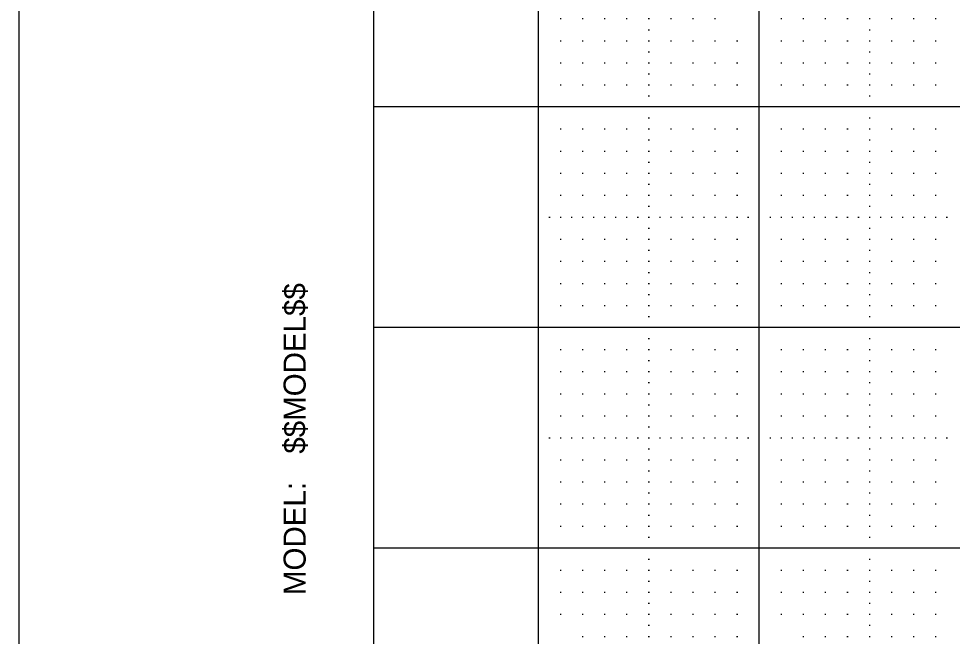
# Model space of a CAD drawing. Extents: x -1.3 to 32.7, y -0.7 to 21.3.
# Drawn here: x -1.263 to 2.967, y 4.893 to 7.693 of the extents above; entities that cross this region are included whole.
import ezdxf

# ---------------------------------------------------------------- set-up
doc = ezdxf.new("R2010")
doc.units = 0
for name, color, linetype in [('Level 1', 7, 'Continuous'), ('Level 5', 7, 'Continuous'), ('Level 63', 7, 'Continuous'), ('R_Border_Dark', 7, 'Continuous')]:
    doc.layers.add(name, color=color, linetype=linetype)

msp = doc.modelspace()

# ---------------------------------------------------------------- linework, layer by layer
at = {"layer": 'Level 1'}
for p, q in [((-1.263, 21.273), (-1.263, -0.727)), ((0.3463, -0.001), (0.3463, 20.545))]:
    msp.add_line(p, q, dxfattribs=at)
at = {"layer": 'Level 5'}
for p, q in [((1.1898, 7.693), (1.1948, 7.693)), ((1.2898, 7.693), (1.2948, 7.693)), ((1.3898, 7.693), (1.3948, 7.693)), ((1.4898, 7.693), (1.4948, 7.693)), ((1.5898, 7.693), (1.5948, 7.693)), ((1.6898, 7.693), (1.6948, 7.693)), ((1.7898, 7.693), (1.7948, 7.693)), ((1.8898, 7.693), (1.8948, 7.693)), ((2.1898, 7.693), (2.1948, 7.693)), ((2.2898, 7.693), (2.2948, 7.693)), ((2.3898, 7.693), (2.3948, 7.693)), ((2.4898, 7.693), (2.4948, 7.693)), ((2.5898, 7.693), (2.5948, 7.693)), ((2.6898, 7.693), (2.6948, 7.693)), ((2.7898, 7.693), (2.7948, 7.693)), ((2.8898, 7.693), (2.8948, 7.693)), ((1.5898, 7.643), (1.5948, 7.643)), ((2.5898, 7.643), (2.5948, 7.643)), ((1.1898, 7.593), (1.1948, 7.593)), ((1.2898, 7.593), (1.2948, 7.593)), ((1.3898, 7.593), (1.3948, 7.593)), ((1.4898, 7.593), (1.4948, 7.593)), ((1.5898, 7.593), (1.5948, 7.593)), ((1.6898, 7.593), (1.6948, 7.593)), ((1.7898, 7.593), (1.7948, 7.593)), ((1.8898, 7.593), (1.8948, 7.593)), ((1.9898, 7.593), (1.9948, 7.593)), ((2.1898, 7.593), (2.1948, 7.593)), ((2.2898, 7.593), (2.2948, 7.593)), ((2.3898, 7.593), (2.3948, 7.593)), ((2.4898, 7.593), (2.4948, 7.593)), ((2.5898, 7.593), (2.5948, 7.593)), ((2.6898, 7.593), (2.6948, 7.593)), ((2.7898, 7.593), (2.7948, 7.593)), ((2.8898, 7.593), (2.8948, 7.593)), ((1.5898, 7.543), (1.5948, 7.543)), ((2.5898, 7.543), (2.5948, 7.543)), ((1.1898, 7.493), (1.1948, 7.493)), ((1.2898, 7.493), (1.2948, 7.493)), ((1.3898, 7.493), (1.3948, 7.493)), ((1.4898, 7.493), (1.4948, 7.493)), ((1.5898, 7.493), (1.5948, 7.493)), ((1.6898, 7.493), (1.6948, 7.493)), ((1.7898, 7.493), (1.7948, 7.493)), ((1.8898, 7.493), (1.8948, 7.493)), ((1.9898, 7.493), (1.9948, 7.493)), ((2.1898, 7.493), (2.1948, 7.493)), ((2.2898, 7.493), (2.2948, 7.493)), ((2.3898, 7.493), (2.3948, 7.493)), ((2.4898, 7.493), (2.4948, 7.493)), ((2.5898, 7.493), (2.5948, 7.493)), ((2.6898, 7.493), (2.6948, 7.493)), ((2.7898, 7.493), (2.7948, 7.493)), ((2.8898, 7.493), (2.8948, 7.493)), ((1.5898, 7.443), (1.5948, 7.443)), ((2.5898, 7.443), (2.5948, 7.443)), ((1.1898, 7.393), (1.1948, 7.393)), ((1.2898, 7.393), (1.2948, 7.393)), ((1.3898, 7.393), (1.3948, 7.393)), ((1.4898, 7.393), (1.4948, 7.393)), ((1.5898, 7.393), (1.5948, 7.393)), ((1.6898, 7.393), (1.6948, 7.393)), ((1.7898, 7.393), (1.7948, 7.393)), ((1.8898, 7.393), (1.8948, 7.393)), ((1.9898, 7.393), (1.9948, 7.393)), ((2.1898, 7.393), (2.1948, 7.393)), ((2.2898, 7.393), (2.2948, 7.393)), ((2.3898, 7.393), (2.3948, 7.393)), ((2.4898, 7.393), (2.4948, 7.393)), ((2.5898, 7.393), (2.5948, 7.393)), ((2.6898, 7.393), (2.6948, 7.393)), ((2.7898, 7.393), (2.7948, 7.393)), ((2.8898, 7.393), (2.8948, 7.393)), ((1.5898, 7.343), (1.5948, 7.343)), ((2.5898, 7.343), (2.5948, 7.343)), ((1.5898, 7.243), (1.5948, 7.243)), ((2.5898, 7.243), (2.5948, 7.243)), ((1.1898, 7.193), (1.1948, 7.193)), ((1.2898, 7.193), (1.2948, 7.193)), ((1.3898, 7.193), (1.3948, 7.193)), ((1.4898, 7.193), (1.4948, 7.193)), ((1.5898, 7.193), (1.5948, 7.193)), ((1.6898, 7.193), (1.6948, 7.193)), ((1.7898, 7.193), (1.7948, 7.193)), ((1.8898, 7.193), (1.8948, 7.193)), ((1.9898, 7.193), (1.9948, 7.193)), ((2.1898, 7.193), (2.1948, 7.193)), ((2.2898, 7.193), (2.2948, 7.193)), ((2.3898, 7.193), (2.3948, 7.193)), ((2.4898, 7.193), (2.4948, 7.193)), ((2.5898, 7.193), (2.5948, 7.193)), ((2.6898, 7.193), (2.6948, 7.193)), ((2.7898, 7.193), (2.7948, 7.193)), ((2.8898, 7.193), (2.8948, 7.193)), ((1.5898, 7.143), (1.5948, 7.143)), ((2.5898, 7.143), (2.5948, 7.143)), ((1.1898, 7.093), (1.1948, 7.093)), ((1.2898, 7.093), (1.2948, 7.093)), ((1.3898, 7.093), (1.3948, 7.093)), ((1.4898, 7.093), (1.4948, 7.093)), ((1.5898, 7.093), (1.5948, 7.093)), ((1.6898, 7.093), (1.6948, 7.093)), ((1.7898, 7.093), (1.7948, 7.093)), ((1.8898, 7.093), (1.8948, 7.093)), ((1.9898, 7.093), (1.9948, 7.093)), ((2.1898, 7.093), (2.1948, 7.093)), ((2.2898, 7.093), (2.2948, 7.093)), ((2.3898, 7.093), (2.3948, 7.093)), ((2.4898, 7.093), (2.4948, 7.093)), ((2.5898, 7.093), (2.5948, 7.093)), ((2.6898, 7.093), (2.6948, 7.093)), ((2.7898, 7.093), (2.7948, 7.093)), ((2.8898, 7.093), (2.8948, 7.093)), ((1.5898, 7.043), (1.5948, 7.043)), ((2.5898, 7.043), (2.5948, 7.043)), ((1.1898, 6.993), (1.1948, 6.993)), ((1.2898, 6.993), (1.2948, 6.993)), ((1.3898, 6.993), (1.3948, 6.993)), ((1.4898, 6.993), (1.4948, 6.993)), ((1.5898, 6.993), (1.5948, 6.993)), ((1.6898, 6.993), (1.6948, 6.993)), ((1.7898, 6.993), (1.7948, 6.993)), ((1.8898, 6.993), (1.8948, 6.993)), ((1.9898, 6.993), (1.9948, 6.993)), ((2.1898, 6.993), (2.1948, 6.993)), ((2.2898, 6.993), (2.2948, 6.993)), ((2.3898, 6.993), (2.3948, 6.993)), ((2.4898, 6.993), (2.4948, 6.993)), ((2.5898, 6.993), (2.5948, 6.993)), ((2.6898, 6.993), (2.6948, 6.993)), ((2.7898, 6.993), (2.7948, 6.993)), ((2.8898, 6.993), (2.8948, 6.993)), ((1.5898, 6.943), (1.5948, 6.943)), ((2.5898, 6.943), (2.5948, 6.943)), ((1.1898, 6.893), (1.1948, 6.893)), ((1.2898, 6.893), (1.2948, 6.893)), ((1.3898, 6.893), (1.3948, 6.893)), ((1.4898, 6.893), (1.4948, 6.893)), ((1.5898, 6.893), (1.5948, 6.893)), ((1.6898, 6.893), (1.6948, 6.893)), ((1.7898, 6.893), (1.7948, 6.893)), ((1.8898, 6.893), (1.8948, 6.893)), ((1.9898, 6.893), (1.9948, 6.893)), ((2.1898, 6.893), (2.1948, 6.893)), ((2.2898, 6.893), (2.2948, 6.893)), ((2.3898, 6.893), (2.3948, 6.893)), ((2.4898, 6.893), (2.4948, 6.893)), ((2.5898, 6.893), (2.5948, 6.893)), ((2.6898, 6.893), (2.6948, 6.893)), ((2.7898, 6.893), (2.7948, 6.893)), ((2.8898, 6.893), (2.8948, 6.893)), ((1.5898, 6.843), (1.5948, 6.843)), ((2.5898, 6.843), (2.5948, 6.843)), ((1.1398, 6.793), (1.1448, 6.793)), ((1.1898, 6.793), (1.1948, 6.793)), ((1.2398, 6.793), (1.2448, 6.793)), ((1.2898, 6.793), (1.2948, 6.793)), ((1.3398, 6.793), (1.3448, 6.793)), ((1.3898, 6.793), (1.3948, 6.793)), ((1.4398, 6.793), (1.4448, 6.793)), ((1.4898, 6.793), (1.4948, 6.793)), ((1.5398, 6.793), (1.5448, 6.793)), ((1.5898, 6.793), (1.5948, 6.793)), ((1.6398, 6.793), (1.6448, 6.793)), ((1.6898, 6.793), (1.6948, 6.793)), ((1.7398, 6.793), (1.7448, 6.793)), ((1.7898, 6.793), (1.7948, 6.793)), ((1.8398, 6.793), (1.8448, 6.793)), ((1.8898, 6.793), (1.8948, 6.793)), ((1.9398, 6.793), (1.9448, 6.793)), ((1.9898, 6.793), (1.9948, 6.793)), ((2.0398, 6.793), (2.0448, 6.793)), ((2.1398, 6.793), (2.1448, 6.793)), ((2.1898, 6.793), (2.1948, 6.793)), ((2.2398, 6.793), (2.2448, 6.793)), ((2.2898, 6.793), (2.2948, 6.793)), ((2.3398, 6.793), (2.3448, 6.793)), ((2.3898, 6.793), (2.3948, 6.793)), ((2.4398, 6.793), (2.4448, 6.793)), ((2.4898, 6.793), (2.4948, 6.793)), ((2.5398, 6.793), (2.5448, 6.793)), ((2.5898, 6.793), (2.5948, 6.793)), ((2.6398, 6.793), (2.6448, 6.793)), ((2.6898, 6.793), (2.6948, 6.793)), ((2.7398, 6.793), (2.7448, 6.793)), ((2.7898, 6.793), (2.7948, 6.793)), ((2.8398, 6.793), (2.8448, 6.793)), ((2.8898, 6.793), (2.8948, 6.793)), ((2.9398, 6.793), (2.9448, 6.793)), ((1.5898, 6.743), (1.5948, 6.743)), ((2.5898, 6.743), (2.5948, 6.743)), ((1.1898, 6.693), (1.1948, 6.693)), ((1.2898, 6.693), (1.2948, 6.693)), ((1.3898, 6.693), (1.3948, 6.693)), ((1.4898, 6.693), (1.4948, 6.693)), ((1.5898, 6.693), (1.5948, 6.693)), ((1.6898, 6.693), (1.6948, 6.693)), ((1.7898, 6.693), (1.7948, 6.693)), ((1.8898, 6.693), (1.8948, 6.693)), ((1.9898, 6.693), (1.9948, 6.693)), ((2.1898, 6.693), (2.1948, 6.693)), ((2.2898, 6.693), (2.2948, 6.693)), ((2.3898, 6.693), (2.3948, 6.693)), ((2.4898, 6.693), (2.4948, 6.693)), ((2.5898, 6.693), (2.5948, 6.693)), ((2.6898, 6.693), (2.6948, 6.693)), ((2.7898, 6.693), (2.7948, 6.693)), ((2.8898, 6.693), (2.8948, 6.693)), ((1.5898, 6.643), (1.5948, 6.643)), ((2.5898, 6.643), (2.5948, 6.643)), ((1.1898, 6.593), (1.1948, 6.593)), ((1.2898, 6.593), (1.2948, 6.593)), ((1.3898, 6.593), (1.3948, 6.593)), ((1.4898, 6.593), (1.4948, 6.593)), ((1.5898, 6.593), (1.5948, 6.593)), ((1.6898, 6.593), (1.6948, 6.593)), ((1.7898, 6.593), (1.7948, 6.593)), ((1.8898, 6.593), (1.8948, 6.593)), ((1.9898, 6.593), (1.9948, 6.593)), ((2.1898, 6.593), (2.1948, 6.593)), ((2.2898, 6.593), (2.2948, 6.593)), ((2.3898, 6.593), (2.3948, 6.593)), ((2.4898, 6.593), (2.4948, 6.593)), ((2.5898, 6.593), (2.5948, 6.593)), ((2.6898, 6.593), (2.6948, 6.593)), ((2.7898, 6.593), (2.7948, 6.593)), ((2.8898, 6.593), (2.8948, 6.593)), ((1.5898, 6.543), (1.5948, 6.543)), ((2.5898, 6.543), (2.5948, 6.543)), ((1.1898, 6.493), (1.1948, 6.493)), ((1.2898, 6.493), (1.2948, 6.493)), ((1.3898, 6.493), (1.3948, 6.493)), ((1.4898, 6.493), (1.4948, 6.493)), ((1.5898, 6.493), (1.5948, 6.493)), ((1.6898, 6.493), (1.6948, 6.493)), ((1.7898, 6.493), (1.7948, 6.493)), ((1.8898, 6.493), (1.8948, 6.493)), ((1.9898, 6.493), (1.9948, 6.493)), ((2.1898, 6.493), (2.1948, 6.493)), ((2.2898, 6.493), (2.2948, 6.493)), ((2.3898, 6.493), (2.3948, 6.493)), ((2.4898, 6.493), (2.4948, 6.493)), ((2.5898, 6.493), (2.5948, 6.493)), ((2.6898, 6.493), (2.6948, 6.493)), ((2.7898, 6.493), (2.7948, 6.493)), ((2.8898, 6.493), (2.8948, 6.493)), ((1.5898, 6.443), (1.5948, 6.443)), ((2.5898, 6.443), (2.5948, 6.443)), ((1.1898, 6.393), (1.1948, 6.393)), ((1.2898, 6.393), (1.2948, 6.393)), ((1.3898, 6.393), (1.3948, 6.393)), ((1.4898, 6.393), (1.4948, 6.393)), ((1.5898, 6.393), (1.5948, 6.393)), ((1.6898, 6.393), (1.6948, 6.393)), ((1.7898, 6.393), (1.7948, 6.393)), ((1.8898, 6.393), (1.8948, 6.393)), ((1.9898, 6.393), (1.9948, 6.393)), ((2.1898, 6.393), (2.1948, 6.393)), ((2.2898, 6.393), (2.2948, 6.393)), ((2.3898, 6.393), (2.3948, 6.393)), ((2.4898, 6.393), (2.4948, 6.393)), ((2.5898, 6.393), (2.5948, 6.393)), ((2.6898, 6.393), (2.6948, 6.393)), ((2.7898, 6.393), (2.7948, 6.393)), ((2.8898, 6.393), (2.8948, 6.393)), ((1.5898, 6.343), (1.5948, 6.343)), ((2.5898, 6.343), (2.5948, 6.343)), ((1.5898, 6.243), (1.5948, 6.243)), ((2.5898, 6.243), (2.5948, 6.243)), ((1.1898, 6.193), (1.1948, 6.193)), ((1.2898, 6.193), (1.2948, 6.193)), ((1.3898, 6.193), (1.3948, 6.193)), ((1.4898, 6.193), (1.4948, 6.193)), ((1.5898, 6.193), (1.5948, 6.193)), ((1.6898, 6.193), (1.6948, 6.193)), ((1.7898, 6.193), (1.7948, 6.193)), ((1.8898, 6.193), (1.8948, 6.193)), ((1.9898, 6.193), (1.9948, 6.193)), ((2.1898, 6.193), (2.1948, 6.193)), ((2.2898, 6.193), (2.2948, 6.193)), ((2.3898, 6.193), (2.3948, 6.193)), ((2.4898, 6.193), (2.4948, 6.193)), ((2.5898, 6.193), (2.5948, 6.193)), ((2.6898, 6.193), (2.6948, 6.193)), ((2.7898, 6.193), (2.7948, 6.193)), ((2.8898, 6.193), (2.8948, 6.193)), ((1.5898, 6.143), (1.5948, 6.143)), ((2.5898, 6.143), (2.5948, 6.143)), ((1.1898, 6.093), (1.1948, 6.093)), ((1.2898, 6.093), (1.2948, 6.093)), ((1.3898, 6.093), (1.3948, 6.093)), ((1.4898, 6.093), (1.4948, 6.093)), ((1.5898, 6.093), (1.5948, 6.093)), ((1.6898, 6.093), (1.6948, 6.093)), ((1.7898, 6.093), (1.7948, 6.093)), ((1.8898, 6.093), (1.8948, 6.093)), ((1.9898, 6.093), (1.9948, 6.093)), ((2.1898, 6.093), (2.1948, 6.093)), ((2.2898, 6.093), (2.2948, 6.093)), ((2.3898, 6.093), (2.3948, 6.093)), ((2.4898, 6.093), (2.4948, 6.093)), ((2.5898, 6.093), (2.5948, 6.093)), ((2.6898, 6.093), (2.6948, 6.093)), ((2.7898, 6.093), (2.7948, 6.093)), ((2.8898, 6.093), (2.8948, 6.093)), ((1.5898, 6.043), (1.5948, 6.043)), ((2.5898, 6.043), (2.5948, 6.043)), ((1.1898, 5.993), (1.1948, 5.993)), ((1.2898, 5.993), (1.2948, 5.993)), ((1.3898, 5.993), (1.3948, 5.993)), ((1.4898, 5.993), (1.4948, 5.993)), ((1.5898, 5.993), (1.5948, 5.993)), ((1.6898, 5.993), (1.6948, 5.993)), ((1.7898, 5.993), (1.7948, 5.993)), ((1.8898, 5.993), (1.8948, 5.993)), ((1.9898, 5.993), (1.9948, 5.993)), ((2.1898, 5.993), (2.1948, 5.993)), ((2.2898, 5.993), (2.2948, 5.993)), ((2.3898, 5.993), (2.3948, 5.993)), ((2.4898, 5.993), (2.4948, 5.993)), ((2.5898, 5.993), (2.5948, 5.993)), ((2.6898, 5.993), (2.6948, 5.993)), ((2.7898, 5.993), (2.7948, 5.993)), ((2.8898, 5.993), (2.8948, 5.993)), ((1.5898, 5.943), (1.5948, 5.943)), ((2.5898, 5.943), (2.5948, 5.943)), ((1.1898, 5.893), (1.1948, 5.893)), ((1.2898, 5.893), (1.2948, 5.893)), ((1.3898, 5.893), (1.3948, 5.893)), ((1.4898, 5.893), (1.4948, 5.893)), ((1.5898, 5.893), (1.5948, 5.893)), ((1.6898, 5.893), (1.6948, 5.893)), ((1.7898, 5.893), (1.7948, 5.893)), ((1.8898, 5.893), (1.8948, 5.893)), ((1.9898, 5.893), (1.9948, 5.893)), ((2.1898, 5.893), (2.1948, 5.893)), ((2.2898, 5.893), (2.2948, 5.893)), ((2.3898, 5.893), (2.3948, 5.893)), ((2.4898, 5.893), (2.4948, 5.893)), ((2.5898, 5.893), (2.5948, 5.893)), ((2.6898, 5.893), (2.6948, 5.893)), ((2.7898, 5.893), (2.7948, 5.893)), ((2.8898, 5.893), (2.8948, 5.893)), ((1.5898, 5.843), (1.5948, 5.843)), ((2.5898, 5.843), (2.5948, 5.843)), ((1.1398, 5.793), (1.1448, 5.793)), ((1.1898, 5.793), (1.1948, 5.793)), ((1.2398, 5.793), (1.2448, 5.793)), ((1.2898, 5.793), (1.2948, 5.793)), ((1.3398, 5.793), (1.3448, 5.793)), ((1.3898, 5.793), (1.3948, 5.793)), ((1.4398, 5.793), (1.4448, 5.793)), ((1.4898, 5.793), (1.4948, 5.793)), ((1.5398, 5.793), (1.5448, 5.793)), ((1.5898, 5.793), (1.5948, 5.793)), ((1.6398, 5.793), (1.6448, 5.793)), ((1.6898, 5.793), (1.6948, 5.793)), ((1.7398, 5.793), (1.7448, 5.793)), ((1.7898, 5.793), (1.7948, 5.793)), ((1.8398, 5.793), (1.8448, 5.793)), ((1.8898, 5.793), (1.8948, 5.793)), ((1.9398, 5.793), (1.9448, 5.793)), ((1.9898, 5.793), (1.9948, 5.793)), ((2.0398, 5.793), (2.0448, 5.793)), ((2.1398, 5.793), (2.1448, 5.793)), ((2.1898, 5.793), (2.1948, 5.793)), ((2.2398, 5.793), (2.2448, 5.793)), ((2.2898, 5.793), (2.2948, 5.793)), ((2.3398, 5.793), (2.3448, 5.793)), ((2.3898, 5.793), (2.3948, 5.793)), ((2.4398, 5.793), (2.4448, 5.793)), ((2.4898, 5.793), (2.4948, 5.793)), ((2.5398, 5.793), (2.5448, 5.793)), ((2.5898, 5.793), (2.5948, 5.793)), ((2.6398, 5.793), (2.6448, 5.793)), ((2.6898, 5.793), (2.6948, 5.793)), ((2.7398, 5.793), (2.7448, 5.793)), ((2.7898, 5.793), (2.7948, 5.793)), ((2.8398, 5.793), (2.8448, 5.793)), ((2.8898, 5.793), (2.8948, 5.793)), ((2.9398, 5.793), (2.9448, 5.793)), ((1.5898, 5.743), (1.5948, 5.743)), ((2.5898, 5.743), (2.5948, 5.743)), ((1.1898, 5.693), (1.1948, 5.693)), ((1.2898, 5.693), (1.2948, 5.693)), ((1.3898, 5.693), (1.3948, 5.693)), ((1.4898, 5.693), (1.4948, 5.693)), ((1.5898, 5.693), (1.5948, 5.693)), ((1.6898, 5.693), (1.6948, 5.693)), ((1.7898, 5.693), (1.7948, 5.693)), ((1.8898, 5.693), (1.8948, 5.693)), ((1.9898, 5.693), (1.9948, 5.693)), ((2.1898, 5.693), (2.1948, 5.693)), ((2.2898, 5.693), (2.2948, 5.693)), ((2.3898, 5.693), (2.3948, 5.693)), ((2.4898, 5.693), (2.4948, 5.693)), ((2.5898, 5.693), (2.5948, 5.693)), ((2.6898, 5.693), (2.6948, 5.693)), ((2.7898, 5.693), (2.7948, 5.693)), ((2.8898, 5.693), (2.8948, 5.693)), ((1.5898, 5.643), (1.5948, 5.643)), ((2.5898, 5.643), (2.5948, 5.643)), ((1.1898, 5.593), (1.1948, 5.593)), ((1.2898, 5.593), (1.2948, 5.593)), ((1.3898, 5.593), (1.3948, 5.593)), ((1.4898, 5.593), (1.4948, 5.593)), ((1.5898, 5.593), (1.5948, 5.593)), ((1.6898, 5.593), (1.6948, 5.593)), ((1.7898, 5.593), (1.7948, 5.593)), ((1.8898, 5.593), (1.8948, 5.593)), ((1.9898, 5.593), (1.9948, 5.593)), ((2.1898, 5.593), (2.1948, 5.593)), ((2.2898, 5.593), (2.2948, 5.593)), ((2.3898, 5.593), (2.3948, 5.593)), ((2.4898, 5.593), (2.4948, 5.593)), ((2.5898, 5.593), (2.5948, 5.593)), ((2.6898, 5.593), (2.6948, 5.593)), ((2.7898, 5.593), (2.7948, 5.593)), ((2.8898, 5.593), (2.8948, 5.593)), ((1.5898, 5.543), (1.5948, 5.543)), ((2.5898, 5.543), (2.5948, 5.543)), ((1.1898, 5.493), (1.1948, 5.493)), ((1.2898, 5.493), (1.2948, 5.493)), ((1.3898, 5.493), (1.3948, 5.493)), ((1.4898, 5.493), (1.4948, 5.493)), ((1.5898, 5.493), (1.5948, 5.493)), ((1.6898, 5.493), (1.6948, 5.493)), ((1.7898, 5.493), (1.7948, 5.493)), ((1.8898, 5.493), (1.8948, 5.493)), ((1.9898, 5.493), (1.9948, 5.493)), ((2.1898, 5.493), (2.1948, 5.493)), ((2.2898, 5.493), (2.2948, 5.493)), ((2.3898, 5.493), (2.3948, 5.493)), ((2.4898, 5.493), (2.4948, 5.493)), ((2.5898, 5.493), (2.5948, 5.493)), ((2.6898, 5.493), (2.6948, 5.493)), ((2.7898, 5.493), (2.7948, 5.493)), ((2.8898, 5.493), (2.8948, 5.493)), ((1.5898, 5.443), (1.5948, 5.443)), ((2.5898, 5.443), (2.5948, 5.443)), ((1.1898, 5.393), (1.1948, 5.393)), ((1.2898, 5.393), (1.2948, 5.393)), ((1.3898, 5.393), (1.3948, 5.393)), ((1.4898, 5.393), (1.4948, 5.393)), ((1.5898, 5.393), (1.5948, 5.393)), ((1.6898, 5.393), (1.6948, 5.393)), ((1.7898, 5.393), (1.7948, 5.393)), ((1.8898, 5.393), (1.8948, 5.393)), ((1.9898, 5.393), (1.9948, 5.393)), ((2.1898, 5.393), (2.1948, 5.393)), ((2.2898, 5.393), (2.2948, 5.393)), ((2.3898, 5.393), (2.3948, 5.393)), ((2.4898, 5.393), (2.4948, 5.393)), ((2.5898, 5.393), (2.5948, 5.393)), ((2.6898, 5.393), (2.6948, 5.393)), ((2.7898, 5.393), (2.7948, 5.393)), ((2.8898, 5.393), (2.8948, 5.393)), ((1.5898, 5.343), (1.5948, 5.343)), ((2.5898, 5.343), (2.5948, 5.343)), ((1.5898, 5.243), (1.5948, 5.243)), ((2.5898, 5.243), (2.5948, 5.243)), ((1.1898, 5.193), (1.1948, 5.193)), ((1.2898, 5.193), (1.2948, 5.193)), ((1.3898, 5.193), (1.3948, 5.193)), ((1.4898, 5.193), (1.4948, 5.193)), ((1.5898, 5.193), (1.5948, 5.193)), ((1.6898, 5.193), (1.6948, 5.193)), ((1.7898, 5.193), (1.7948, 5.193)), ((1.8898, 5.193), (1.8948, 5.193)), ((1.9898, 5.193), (1.9948, 5.193)), ((2.1898, 5.193), (2.1948, 5.193)), ((2.2898, 5.193), (2.2948, 5.193)), ((2.3898, 5.193), (2.3948, 5.193)), ((2.4898, 5.193), (2.4948, 5.193)), ((2.5898, 5.193), (2.5948, 5.193)), ((2.6898, 5.193), (2.6948, 5.193)), ((2.7898, 5.193), (2.7948, 5.193)), ((2.8898, 5.193), (2.8948, 5.193)), ((1.5898, 5.143), (1.5948, 5.143)), ((2.5898, 5.143), (2.5948, 5.143)), ((1.1898, 5.093), (1.1948, 5.093)), ((1.2898, 5.093), (1.2948, 5.093)), ((1.3898, 5.093), (1.3948, 5.093)), ((1.4898, 5.093), (1.4948, 5.093)), ((1.5898, 5.093), (1.5948, 5.093)), ((1.6898, 5.093), (1.6948, 5.093)), ((1.7898, 5.093), (1.7948, 5.093)), ((1.8898, 5.093), (1.8948, 5.093)), ((1.9898, 5.093), (1.9948, 5.093)), ((2.1898, 5.093), (2.1948, 5.093)), ((2.2898, 5.093), (2.2948, 5.093)), ((2.3898, 5.093), (2.3948, 5.093)), ((2.4898, 5.093), (2.4948, 5.093)), ((2.5898, 5.093), (2.5948, 5.093)), ((2.6898, 5.093), (2.6948, 5.093)), ((2.7898, 5.093), (2.7948, 5.093)), ((2.8898, 5.093), (2.8948, 5.093)), ((1.5898, 5.043), (1.5948, 5.043)), ((2.5898, 5.043), (2.5948, 5.043)), ((1.1898, 4.993), (1.1948, 4.993)), ((1.2898, 4.993), (1.2948, 4.993)), ((1.3898, 4.993), (1.3948, 4.993)), ((1.4898, 4.993), (1.4948, 4.993)), ((1.5898, 4.993), (1.5948, 4.993)), ((1.6898, 4.993), (1.6948, 4.993)), ((1.7898, 4.993), (1.7948, 4.993)), ((1.8898, 4.993), (1.8948, 4.993)), ((1.9898, 4.993), (1.9948, 4.993)), ((2.1898, 4.993), (2.1948, 4.993)), ((2.2898, 4.993), (2.2948, 4.993)), ((2.3898, 4.993), (2.3948, 4.993)), ((2.4898, 4.993), (2.4948, 4.993)), ((2.5898, 4.993), (2.5948, 4.993)), ((2.6898, 4.993), (2.6948, 4.993)), ((2.7898, 4.993), (2.7948, 4.993)), ((2.8898, 4.993), (2.8948, 4.993)), ((1.5898, 4.943), (1.5948, 4.943)), ((2.5898, 4.943), (2.5948, 4.943)), ((1.2898, 4.893), (1.2948, 4.893)), ((1.3898, 4.893), (1.3948, 4.893)), ((1.4898, 4.893), (1.4948, 4.893)), ((1.5898, 4.893), (1.5948, 4.893)), ((1.6898, 4.893), (1.6948, 4.893)), ((1.7898, 4.893), (1.7948, 4.893)), ((1.8898, 4.893), (1.8948, 4.893)), ((1.9898, 4.893), (1.9948, 4.893)), ((2.2898, 4.893), (2.2948, 4.893)), ((2.3898, 4.893), (2.3948, 4.893)), ((2.4898, 4.893), (2.4948, 4.893)), ((2.5898, 4.893), (2.5948, 4.893)), ((2.6898, 4.893), (2.6948, 4.893)), ((2.7898, 4.893), (2.7948, 4.893)), ((2.8898, 4.893), (2.8948, 4.893))]:
    msp.add_line(p, q, dxfattribs=at)
at = {"layer": 'Level 63'}
msp.add_lwpolyline([(-1.263, -0.727), (32.737, -0.727), (32.737, 21.273), (-1.263, 21.273)], close=True, dxfattribs=at)
msp.add_lwpolyline([(31.0923, 10.293), (31.0923, 0.293), (1.0923, 0.293), (1.0923, 8.293)], dxfattribs=at)
at = {"layer": 'R_Border_Dark'}
for p, q in [((1.0923, 0.293), (1.0923, 10.293)), ((2.0923, 0.293), (2.0923, 10.293)), ((31.9643, 7.293), (0.3463, 7.293)), ((31.9643, 6.293), (0.3463, 6.293)), ((31.9643, 5.293), (0.3463, 5.293))]:
    msp.add_line(p, q, dxfattribs=at)
msp.add_lwpolyline([(31.0923, 10.293), (31.0923, 0.293), (1.0923, 0.293), (1.0923, 8.293)], dxfattribs=at)

# ---------------------------------------------------------------- texts
at = {"layer": 'Level 1'}
for s, p in [('$$MODEL$$', (0.0373, 5.721)), ('MODEL:', (0.0373, 5.08))]:
    msp.add_text(s, height=0.1, rotation=90, dxfattribs=at).set_placement(p)

doc.saveas('drawing.dxf')
